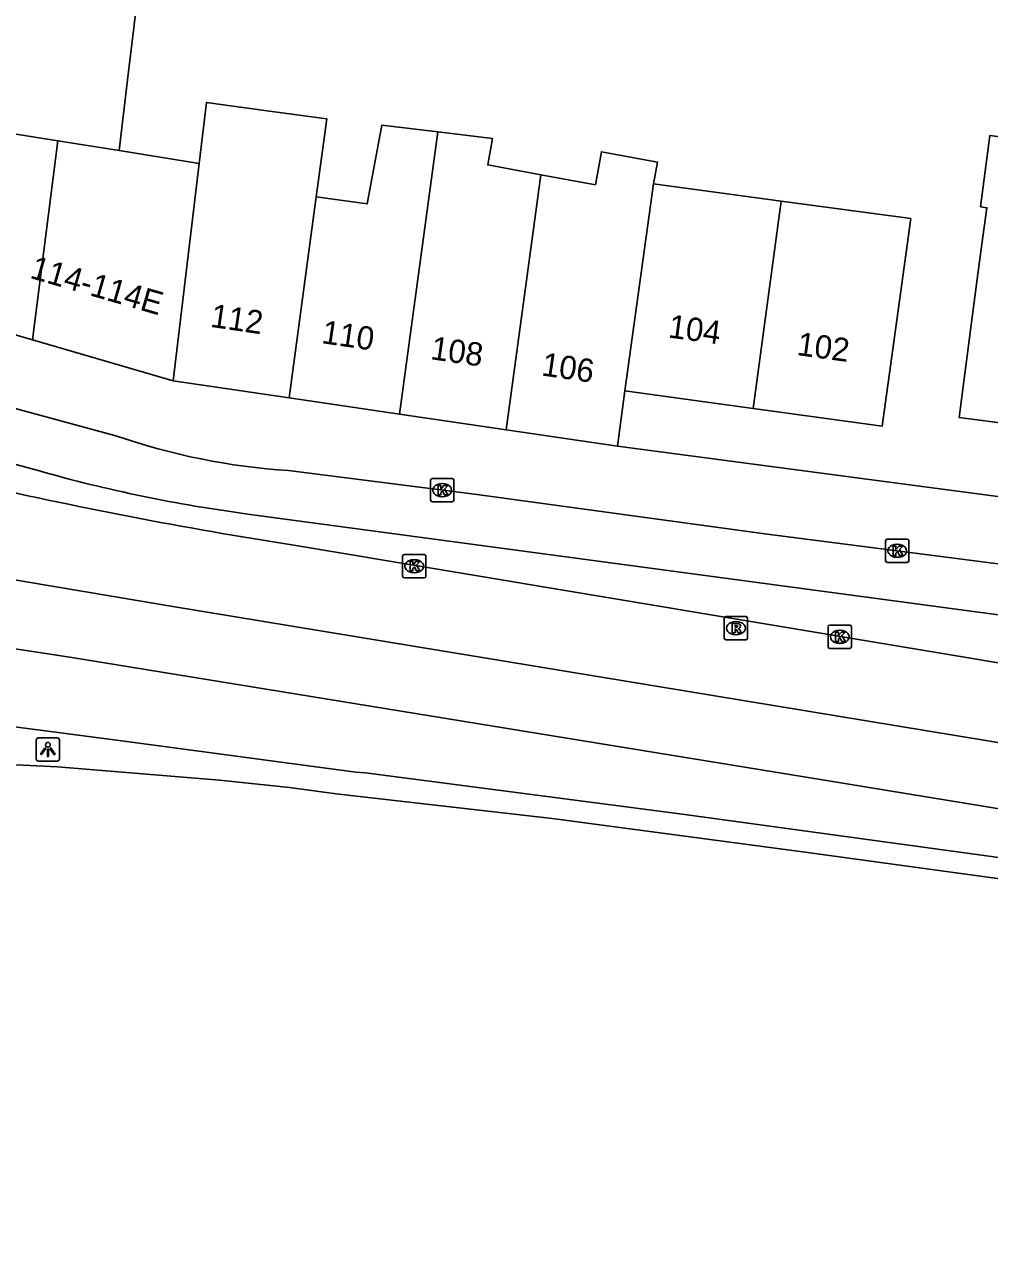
# Model space of a CAD drawing. Extents: x 161845 to 162341, y 381620 to 382158.
# Drawn here: x 161881.4 to 161922.8, y 381625.6 to 381677.9 of the extents above; entities that cross this region are included whole.
import ezdxf

# ---------------------------------------------------------------- set-up
doc = ezdxf.new("R2010")
doc.units = 0
for name, color, linetype in [('IMGEO_Fietspad_open', 7, 'Continuous'), ('IMGEO_Kolk', 7, 'Continuous'), ('IMGEO_Lichtpunt', 7, 'Continuous'), ('IMGEO_Pand', 7, 'Continuous'), ('IMGEO_Pand_nummerreeks', 7, 'Continuous'), ('IMGEO_Rijbaan_regionaal_gesloten', 7, 'Continuous'), ('IMGEO_Rioolput', 7, 'Continuous'), ('IMGEO_Voetpad_open', 7, 'Continuous')]:
    doc.layers.add(name, color=color, linetype=linetype)

msp = doc.modelspace()

# ---------------------------------------------------------------- linework, layer by layer
at = {"layer": 'IMGEO_Fietspad_open'}
for points in [[(161866.029, 381665.604), (161868.739, 381664.771), (161885.319, 381660.279)], [(161870.737, 381661.813), (161881.998, 381658.78)], [(161892.731, 381658.781), (161900.703, 381657.764), (161913.151, 381656.071), (161923.921, 381654.69), (161940.036, 381652.534), (161957.169, 381650.266), (161974.233, 381648.03), (161976.924, 381647.666)], [(161890.986, 381656.917), (161965.669, 381646.893)]]:
    msp.add_lwpolyline(points, dxfattribs=at)
for centre, radius, start, end in [((161894.549, 381686.864), 28.142, 250.8529, 266.2954), ((161899.275, 381719.52), 63.149, 254.12199, 262.45754)]:
    msp.add_arc(centre, radius, start, end, dxfattribs=at)
at = {"layer": 'IMGEO_Kolk'}
for p, q in [((161898.816, 381657.516), (161898.816, 381658.368)), ((161898.891, 381658.442), (161899.743, 381658.442)), ((161899.304, 381658.222), (161899.329, 381658.222)), ((161899.817, 381658.368), (161899.817, 381657.516)), ((161899.327, 381657.662), (161899.302, 381657.662)), ((161899.743, 381657.442), (161898.891, 381657.442)), ((161918.323, 381654.919), (161918.323, 381655.771)), ((161918.398, 381655.845), (161919.25, 381655.845)), ((161918.811, 381655.625), (161918.836, 381655.625)), ((161919.324, 381655.771), (161919.324, 381654.919)), ((161897.617, 381654.254), (161897.617, 381655.106)), ((161897.692, 381655.18), (161898.544, 381655.18)), ((161898.618, 381655.106), (161898.618, 381654.254)), ((161918.834, 381655.065), (161918.809, 381655.065)), ((161898.105, 381654.96), (161898.13, 381654.96)), ((161919.25, 381654.845), (161918.398, 381654.845)), ((161898.544, 381654.18), (161897.692, 381654.18)), ((161898.128, 381654.4), (161898.103, 381654.4)), ((161915.86, 381651.229), (161915.86, 381652.081)), ((161915.935, 381652.155), (161916.787, 381652.155)), ((161916.348, 381651.935), (161916.373, 381651.935)), ((161916.861, 381652.081), (161916.861, 381651.229)), ((161916.371, 381651.375), (161916.346, 381651.375)), ((161916.787, 381651.155), (161915.935, 381651.155))]:
    msp.add_line(p, q, dxfattribs=at)
for points in [[(161898.816, 381657.516), (161898.816, 381658.368)], [(161898.891, 381658.442), (161899.743, 381658.442)], [(161899.137, 381658.142), (161899.26, 381658.142), (161899.26, 381657.991), (161899.39, 381658.142), (161899.554, 381658.142), (161899.408, 381657.991), (161899.561, 381657.742), (161899.409, 381657.742), (161899.324, 381657.906), (161899.26, 381657.839), (161899.26, 381657.742), (161899.137, 381657.742), (161899.137, 381658.142)], [(161899.817, 381658.368), (161899.817, 381657.516)], [(161899.743, 381657.442), (161898.891, 381657.442)], [(161918.323, 381654.919), (161918.323, 381655.771)], [(161918.398, 381655.845), (161919.25, 381655.845)], [(161918.644, 381655.545), (161918.767, 381655.545), (161918.767, 381655.394), (161918.897, 381655.545), (161919.061, 381655.545), (161918.915, 381655.394), (161919.068, 381655.145), (161918.916, 381655.145), (161918.831, 381655.309), (161918.767, 381655.242), (161918.767, 381655.145), (161918.644, 381655.145), (161918.644, 381655.545)], [(161919.324, 381655.771), (161919.324, 381654.919)], [(161897.617, 381654.254), (161897.617, 381655.106)], [(161897.692, 381655.18), (161898.544, 381655.18)], [(161898.618, 381655.106), (161898.618, 381654.254)], [(161897.938, 381654.88), (161898.061, 381654.88), (161898.061, 381654.729), (161898.191, 381654.88), (161898.355, 381654.88), (161898.209, 381654.729), (161898.362, 381654.48), (161898.21, 381654.48), (161898.125, 381654.644), (161898.061, 381654.577), (161898.061, 381654.48), (161897.938, 381654.48), (161897.938, 381654.88)], [(161919.25, 381654.845), (161918.398, 381654.845)], [(161898.544, 381654.18), (161897.692, 381654.18)], [(161915.86, 381651.229), (161915.86, 381652.081)], [(161915.935, 381652.155), (161916.787, 381652.155)], [(161916.181, 381651.855), (161916.304, 381651.855), (161916.304, 381651.704), (161916.434, 381651.855), (161916.598, 381651.855), (161916.452, 381651.704), (161916.605, 381651.455), (161916.453, 381651.455), (161916.368, 381651.619), (161916.304, 381651.552), (161916.304, 381651.455), (161916.181, 381651.455), (161916.181, 381651.855)], [(161916.861, 381652.081), (161916.861, 381651.229)], [(161916.787, 381651.155), (161915.935, 381651.155)]]:
    msp.add_lwpolyline(points, dxfattribs=at)
for centre, start, end in [((161898.893, 381658.366), 91.552, 178.448), ((161898.893, 381658.366), 91.552, 178.448), ((161899.741, 381658.366), 1.552, 88.448), ((161899.741, 381658.366), 1.552, 88.448), ((161898.893, 381657.518), 181.552, 268.448), ((161898.893, 381657.518), 181.552, 268.448), ((161899.741, 381657.518), 271.552, 358.448), ((161899.741, 381657.518), 271.552, 358.448), ((161918.4, 381655.769), 91.552, 178.448), ((161918.4, 381655.769), 91.552, 178.448), ((161919.248, 381655.769), 1.552, 88.448), ((161919.248, 381655.769), 1.552, 88.448), ((161897.694, 381655.104), 91.552, 178.448), ((161897.694, 381655.104), 91.552, 178.448), ((161898.542, 381655.104), 1.552, 88.448), ((161898.542, 381655.104), 1.552, 88.448), ((161918.4, 381654.921), 181.552, 268.448), ((161918.4, 381654.921), 181.552, 268.448), ((161919.248, 381654.921), 271.552, 358.448), ((161919.248, 381654.921), 271.552, 358.448), ((161897.694, 381654.256), 181.552, 268.448), ((161897.694, 381654.256), 181.552, 268.448), ((161898.542, 381654.256), 271.552, 358.448), ((161898.542, 381654.256), 271.552, 358.448), ((161915.937, 381652.079), 91.552, 178.448), ((161915.937, 381652.079), 91.552, 178.448), ((161916.785, 381652.079), 1.552, 88.448), ((161916.785, 381652.079), 1.552, 88.448), ((161915.937, 381651.231), 181.552, 268.448), ((161915.937, 381651.231), 181.552, 268.448), ((161916.785, 381651.231), 271.552, 358.448), ((161916.785, 381651.231), 271.552, 358.448)]:
    msp.add_arc(centre, 0.0765, start, end, dxfattribs=at)
for centre, major_axis, ratio, start_param, end_param in [((161899.303, 381657.942), (-0.387, 0.002), 0.722429, 4.712389, 7.853982), ((161899.328, 381657.942), (-0.39, 0.002), 0.717154, 1.570796, 4.712389), ((161918.81, 381655.345), (-0.387, 0.002), 0.722429, 4.712389, 7.853982), ((161918.835, 381655.345), (-0.39, 0.002), 0.717154, 1.570796, 4.712389), ((161898.104, 381654.68), (-0.387, 0.002), 0.722429, 4.712389, 7.853982), ((161898.129, 381654.68), (-0.39, 0.002), 0.717154, 1.570796, 4.712389), ((161916.347, 381651.655), (-0.387, 0.002), 0.722429, 4.712389, 7.853982), ((161916.372, 381651.655), (-0.39, 0.002), 0.717154, 1.570796, 4.712389)]:
    msp.add_ellipse(centre, major_axis=major_axis, ratio=ratio, start_param=start_param, end_param=end_param, dxfattribs=at)
at = {"layer": 'IMGEO_Lichtpunt'}
for p, q in [((161881.91, 381647.228), (161881.91, 381646.421)), ((161881.91, 381647.228), (161881.91, 381646.421)), ((161882.812, 381647.323), (161882.004, 381647.323)), ((161882.812, 381647.323), (161882.004, 381647.323)), ((161882.906, 381646.421), (161882.906, 381647.228)), ((161882.906, 381646.421), (161882.906, 381647.228)), ((161882.004, 381646.327), (161882.812, 381646.327)), ((161882.004, 381646.327), (161882.812, 381646.327))]:
    msp.add_line(p, q, dxfattribs=at)
for points in [[(161882.284, 381646.892), (161882.323, 381646.864), (161882.135, 381646.602), (161882.097, 381646.629), (161882.284, 381646.892)], [(161882.386, 381646.844), (161882.433, 381646.844), (161882.433, 381646.522), (161882.386, 381646.522), (161882.386, 381646.844)], [(161882.496, 381646.864), (161882.534, 381646.891), (161882.721, 381646.629), (161882.682, 381646.601), (161882.496, 381646.864)]]:
    msp.add_lwpolyline(points, dxfattribs=at)
msp.add_circle((161882.409, 381647.026), 0.0994, dxfattribs=at)
for centre, start, end in [((161882.004, 381647.228), 90, 180), ((161882.004, 381647.228), 90, 180), ((161882.812, 381647.228), 0, 90), ((161882.812, 381647.228), 0, 90), ((161882.004, 381646.421), 180, 270), ((161882.004, 381646.421), 180, 270), ((161882.812, 381646.421), 270, 0), ((161882.812, 381646.421), 270, 360)]:
    msp.add_arc(centre, 0.0946, start, end, dxfattribs=at)
at = {"layer": 'IMGEO_Pand'}
for points in [[(161885.465, 381672.502), (161885.826, 381675.533), (161886.077, 381677.646), (161886.558, 381681.681)], [(161893.913, 381670.513), (161894.367, 381673.867), (161893.29, 381674.013), (161891.916, 381674.199), (161889.207, 381674.566), (161888.896, 381671.955)], [(161877.184, 381673.822), (161882.832, 381672.922)], [(161899.121, 381673.301), (161896.72, 381673.592), (161896.099, 381670.225), (161893.913, 381670.513)], [(161897.485, 381661.208), (161899.121, 381673.301)], [(161903.54, 381671.469), (161901.264, 381671.889), (161901.472, 381673.017), (161899.121, 381673.301)], [(161882.832, 381672.922), (161881.751, 381664.382)], [(161882.832, 381672.922), (161885.465, 381672.502)], [(161928.56, 381667.429), (161923.841, 381668.05), (161924.085, 381669.9), (161925.454, 381669.719), (161925.854, 381672.751), (161922.799, 381673.154), (161922.395, 381670.091), (161922.667, 381670.055), (161922.41, 381668.169), (161922.127, 381666.023), (161921.474, 381661.065), (161927.614, 381660.256)], [(161888.896, 381671.955), (161885.465, 381672.502)], [(161908.368, 381671.071), (161908.542, 381672.011), (161906.144, 381672.454), (161905.882, 381671.037), (161903.54, 381671.469)], [(161888.896, 381671.955), (161887.786, 381662.632)], [(161902.061, 381660.536), (161903.239, 381669.243), (161903.54, 381671.469)], [(161907.147, 381662.199), (161908.368, 381671.071)], [(161913.854, 381670.333), (161908.368, 381671.071)], [(161892.748, 381661.903), (161893.913, 381670.513)], [(161913.854, 381670.333), (161912.64, 381661.448)], [(161912.64, 381661.448), (161918.184, 381660.69), (161918.861, 381665.644), (161919.4, 381669.587), (161913.854, 381670.333)], [(161881.751, 381664.382), (161876.207, 381665.989)], [(161887.786, 381662.632), (161881.751, 381664.382)], [(161892.748, 381661.903), (161887.786, 381662.632)], [(161897.485, 381661.208), (161892.748, 381661.903)], [(161906.825, 381659.836), (161907.147, 381662.199)], [(161907.147, 381662.199), (161912.64, 381661.448)], [(161902.061, 381660.536), (161897.485, 381661.208)], [(161906.825, 381659.836), (161902.061, 381660.536)]]:
    msp.add_lwpolyline(points, dxfattribs=at)
at = {"layer": 'IMGEO_Rijbaan_regionaal_gesloten'}
for points in [[(161869.776, 381655.978), (161887.687, 381652.965), (161964.232, 381640.351), (161981.6, 381637.531), (162040.889, 381629.888), (162052.073, 381628.524), (162065.762, 381627.224)], [(161965.767, 381645.44), (161958.321, 381644.667), (161892.953, 381655.58)], [(161977.994, 381634.916), (161969.971, 381636.522), (161951.098, 381639.708), (161914.926, 381645.64), (161883.44, 381650.767), (161869.396, 381652.918)], [(161977.994, 381634.916), (161973.169, 381635.565), (161948.502, 381638.759), (161926.723, 381641.701), (161909.5, 381644.059), (161896.023, 381645.823), (161895.606, 381645.846), (161885.686, 381647.176), (161868.955, 381649.373)], [(162041.142, 381625.595), (162025.397, 381627.722), (162010.561, 381629.677), (162000, 381631.043), (161996.066, 381631.552), (161984.887, 381633.043), (161972.289, 381634.826), (161957.942, 381636.69), (161940.829, 381638.977), (161927.192, 381640.741), (161914.664, 381642.454), (161904.024, 381643.865), (161894.771, 381644.916), (161892.769, 381645.193), (161889.772, 381645.513), (161882.828, 381646.083), (161874.755, 381646.468), (161868.493, 381646.613)]]:
    msp.add_lwpolyline(points, dxfattribs=at)
msp.add_arc((161924.454, 381856.326), 203.202, 257.05723, 261.08194, dxfattribs=at)
at = {"layer": 'IMGEO_Rioolput'}
for p, q in [((161911.409, 381651.6), (161911.409, 381652.452)), ((161911.484, 381652.526), (161912.336, 381652.526)), ((161912.41, 381652.452), (161912.41, 381651.6)), ((161911.897, 381652.306), (161911.922, 381652.306)), ((161912.336, 381651.526), (161911.484, 381651.526)), ((161911.92, 381651.746), (161911.895, 381651.746))]:
    msp.add_line(p, q, dxfattribs=at)
for points in [[(161911.409, 381651.6), (161911.409, 381652.452)], [(161911.484, 381652.526), (161912.336, 381652.526)], [(161912.41, 381652.452), (161912.41, 381651.6)], [(161911.998, 381652.224), (161911.746, 381652.226), (161911.746, 381651.826)], [(161911.746, 381651.826), (161911.87, 381651.826), (161911.87, 381651.988), (161911.881, 381651.988)], [(161911.924, 381652.145), (161911.87, 381652.145), (161911.87, 381652.064)], [(161911.87, 381652.064), (161911.922, 381652.064)], [(161911.928, 381651.959), (161911.999, 381651.826), (161912.139, 381651.826), (161912.074, 381651.952)], [(161912.336, 381651.526), (161911.484, 381651.526)]]:
    msp.add_lwpolyline(points, dxfattribs=at)
for centre, radius, start, end in [((161911.486, 381652.45), 0.0765, 91.552, 178.448), ((161911.486, 381652.45), 0.0765, 91.552, 178.448), ((161912.334, 381652.45), 0.0765, 1.552, 88.448), ((161912.334, 381652.45), 0.0765, 1.552, 88.448), ((161911.88, 381651.935), 0.0533, 26.0293, 88.6989), ((161911.906, 381652.253), 0.19, 274.7715, 282.9687), ((161911.93, 381652.049), 0.0964, 77.0061, 93.1865), ((161911.944, 381652.106), 0.0378, 276.6634, 79.6772), ((161911.997, 381652.114), 0.109, 350.3612, 89.416), ((161911.995, 381652.114), 0.112, 277.5842, 350.9817), ((161911.979, 381651.899), 0.108, 29.5134, 73.7905), ((161911.486, 381651.602), 0.0765, 181.552, 268.448), ((161911.486, 381651.602), 0.0765, 181.552, 268.448), ((161912.334, 381651.602), 0.0765, 271.552, 358.448), ((161912.334, 381651.602), 0.0765, 271.552, 358.448)]:
    msp.add_arc(centre, radius, start, end, dxfattribs=at)
for centre, major_axis, ratio, start_param, end_param in [((161911.896, 381652.026), (-0.387, 0.002), 0.722429, 4.712389, 7.853982), ((161911.921, 381652.026), (-0.39, 0.002), 0.717154, 1.570796, 4.712389)]:
    msp.add_ellipse(centre, major_axis=major_axis, ratio=ratio, start_param=start_param, end_param=end_param, dxfattribs=at)
at = {"layer": 'IMGEO_Voetpad_open'}
msp.add_lwpolyline([(161944.516, 381654.835), (161906.825, 381659.836)], dxfattribs=at)

# ---------------------------------------------------------------- texts
at = {"layer": 'IMGEO_Pand_nummerreeks'}
for s, rotation, p in [('114-114E', 343.8311, (161881.594, 381667.051)), ('112', 351.652, (161889.344, 381664.948)), ('104', 352.2147, (161908.972, 381664.493)), ('110', 351.6518, (161894.11, 381664.249)), ('108', 351.6518, (161898.781, 381663.563)), ('102', 352.2135, (161914.489, 381663.739)), ('106', 351.6518, (161903.537, 381662.866))]:
    msp.add_text(s, height=1, rotation=rotation, dxfattribs=at).set_placement(p)

doc.saveas('drawing.dxf')
